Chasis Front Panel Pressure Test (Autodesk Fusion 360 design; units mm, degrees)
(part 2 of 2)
sketch "Sketch8" plane through (0, 0, 0) normal (-1, 0, 0) x axis (0, -1, 0)
  line L1 (-12.8306, 47.5808) -> (-6.8306, 47.5808)
  line L2 (-12.8306, 77.5808) -> (-12.8306, 47.5808)
  line L3 (-6.8306, 77.5808) -> (-12.8306, 77.5808)
  line L4 (-6.8306, 97.5808) -> (-6.8306, 77.5808)
  line L5 (-12.8306, 97.5808) -> (-6.8306, 97.5808)
  line L6 (-12.8306, 112.5808) -> (-12.8306, 97.5808)
  line L7 (-60.8306, 112.5808) -> (-12.8306, 112.5808)
  line L8 (-60.8306, 118.5808) -> (-60.8306, 112.5808)
  line L9 (-140.8306, 118.5808) -> (-60.8306, 118.5808)
  line L10 (-140.8306, 112.5808) -> (-140.8306, 118.5808)
  line L11 (-194.8306, 112.5808) -> (-140.8306, 112.5808)
  line L12 (-194.8306, 118.5808) -> (-194.8306, 112.5808)
  line L13 (-274.8306, 118.5808) -> (-194.8306, 118.5808)
  line L14 (-274.8306, 112.5808) -> (-274.8306, 118.5808)
  line L15 (-322.8306, 112.5808) -> (-274.8306, 112.5808)
  line L16 (-322.8306, 97.5808) -> (-322.8306, 112.5808)
  line L17 (-328.8306, 97.5808) -> (-322.8306, 97.5808)
  line L18 (-328.8306, 77.5808) -> (-328.8306, 97.5808)
  line L19 (-322.8306, 77.5808) -> (-328.8306, 77.5808)
  line L20 (-322.8306, 47.5808) -> (-322.8306, 77.5808)
  line L21 (-328.8306, 47.5808) -> (-322.8306, 47.5808)
  line L22 (-328.8306, 27.5808) -> (-328.8306, 47.5808)
  line L23 (-322.8306, 27.5808) -> (-328.8306, 27.5808)
  line L24 (-322.8306, 12.5808) -> (-322.8306, 27.5808)
  line L25 (-274.8306, 12.5808) -> (-322.8306, 12.5808)
  line L26 (-274.8306, 6.5808) -> (-274.8306, 12.5808)
  line L27 (-194.8306, 6.5808) -> (-274.8306, 6.5808)
  line L28 (-194.8306, 12.5808) -> (-194.8306, 6.5808)
  line L29 (-140.8306, 12.5808) -> (-194.8306, 12.5808)
  line L30 (-140.8306, 6.5808) -> (-140.8306, 12.5808)
  line L31 (-60.8306, 6.5808) -> (-140.8306, 6.5808)
  line L32 (-60.8306, 12.5808) -> (-60.8306, 6.5808)
  line L33 (-12.8306, 12.5808) -> (-60.8306, 12.5808)
  line L34 (-12.8306, 27.5808) -> (-12.8306, 12.5808)
  line L35 (-6.8306, 27.5808) -> (-12.8306, 27.5808)
  line L36 (-6.8306, 47.5808) -> (-6.8306, 27.5808)
  line L37 (-295.8805, 70.6308) -> (-295.8805, 54.5308)
  line L38 (-293.4805, 70.6308) -> (-295.8805, 70.6308)
  line L39 (-293.4805, 54.5308) -> (-293.4805, 70.6308)
  line L40 (-295.8805, 54.5308) -> (-293.4805, 54.5308)
  line L41 (-48.6306, 76.0808) -> (-48.6306, 49.0808)
  line L42 (-35.6306, 76.0808) -> (-48.6306, 76.0808)
  line L43 (-35.6306, 49.0808) -> (-35.6306, 76.0808)
  line L44 (-48.6306, 49.0808) -> (-35.6306, 49.0808)
  line L45 (-272.9555, 53.2308) -> (-270.6055, 53.2308)
  line L46 (-274.0555, 70.8308) -> (-274.0555, 54.3308)
  line L47 (-270.6055, 71.9308) -> (-272.9555, 71.9308)
  line L48 (-270.6055, 73.5808) -> (-270.6055, 71.9308)
  line L49 (-267.6055, 71.9308) -> (-267.6055, 73.5808)
  line L50 (-265.2555, 71.9308) -> (-267.6055, 71.9308)
  line L51 (-264.1555, 54.3308) -> (-264.1555, 70.8308)
  line L52 (-267.6055, 53.2308) -> (-265.2555, 53.2308)
  line L53 (-267.6055, 51.5808) -> (-267.6055, 53.2308)
  line L54 (-270.6055, 53.2308) -> (-270.6055, 51.5808)
  line L55 (-204.3306, 80.0808) -> (-204.3306, 55.0808)
  line L56 (-131.3306, 80.0808) -> (-204.3306, 80.0808)
  line L57 (-131.3306, 55.0808) -> (-131.3306, 80.0808)
  line L58 (-204.3306, 55.0808) -> (-131.3306, 55.0808)
  line L59 (-235.1305, 53.2308) -> (-235.1305, 51.5808)
  line L60 (-237.4805, 53.2308) -> (-235.1305, 53.2308)
  line L61 (-238.5805, 70.8308) -> (-238.5805, 54.3308)
  line L62 (-235.1305, 71.9308) -> (-237.4805, 71.9308)
  line L63 (-235.1305, 73.5808) -> (-235.1305, 71.9308)
  line L64 (-232.1305, 71.9308) -> (-232.1305, 73.5808)
  line L65 (-229.7805, 71.9308) -> (-232.1305, 71.9308)
  line L66 (-228.6805, 54.3308) -> (-228.6805, 70.8308)
  line L67 (-232.1305, 53.2308) -> (-229.7805, 53.2308)
  line L68 (-232.1305, 51.5808) -> (-232.1305, 53.2308)
  line L69 (-14.8306, 112.5808) -> (-30.8306, 112.5808)
  line L70 (-25.5806, 91.5808) -> (-25.5806, 107.0808)
  line L71 (-20.0806, 107.0808) -> (-20.0806, 91.5808)
  line L72 (-14.8306, 107.0808) -> (-14.8306, 112.5808)
  line L73 (-30.8306, 107.0808) -> (-14.8306, 107.0808)
  line L74 (-20.0806, 91.5808) -> (-25.5806, 91.5808)
  line L75 (-30.8306, 112.5808) -> (-30.8306, 107.0808)
  circle C1 centre (-22.8306, 27.5808) radius 2.05
  circle C2 centre (-312.8306, 27.5808) radius 2.05
  circle C3 centre (-22.8306, 97.5808) radius 2.05
  circle C4 centre (-312.8306, 97.5808) radius 2.05
  circle C5 centre (-205.3306, 52.0808) radius 1.5
  circle C6 centre (-185.3306, 33.8308) radius 3
  circle C7 centre (-88.4306, 62.5808) radius 11
  circle C8 centre (-200.3306, 33.8308) radius 3
  circle C9 centre (-205.3306, 83.0808) radius 1.5
  arc A1 centre (-272.9555, 54.3308) radius 1.1 clockwise from (-272.9555, 53.2308) to (-274.0555, 54.3308)
  arc A2 centre (-272.9555, 70.8308) radius 1.1 clockwise from (-274.0555, 70.8308) to (-272.9555, 71.9308)
  arc A3 centre (-269.1055, 73.5808) radius 1.5 clockwise from (-270.6055, 73.5808) to (-267.6055, 73.5808)
  arc A4 centre (-265.2555, 70.8308) radius 1.1 clockwise from (-265.2555, 71.9308) to (-264.1555, 70.8308)
  arc A5 centre (-265.2555, 54.3308) radius 1.1 clockwise from (-264.1555, 54.3308) to (-265.2555, 53.2308)
  arc A6 centre (-269.1055, 51.5808) radius 1.5 clockwise from (-267.6055, 51.5808) to (-270.6055, 51.5808)
  circle C10 centre (-130.3306, 83.0808) radius 1.5
  circle C11 centre (-150.3306, 33.8308) radius 3
  circle C12 centre (-135.3306, 33.8308) radius 3
  circle C13 centre (-130.3306, 52.0808) radius 1.5
  arc A7 centre (-237.4805, 54.3308) radius 1.1 clockwise from (-237.4805, 53.2308) to (-238.5805, 54.3308)
  arc A8 centre (-237.4805, 70.8308) radius 1.1 clockwise from (-238.5805, 70.8308) to (-237.4805, 71.9308)
  arc A9 centre (-233.6305, 73.5808) radius 1.5 clockwise from (-235.1305, 73.5808) to (-232.1305, 73.5808)
  arc A10 centre (-229.7805, 70.8308) radius 1.1 clockwise from (-229.7805, 71.9308) to (-228.6805, 70.8308)
  arc A11 centre (-229.7805, 54.3308) radius 1.1 clockwise from (-228.6805, 54.3308) to (-229.7805, 53.2308)
  arc A12 centre (-233.6305, 51.5808) radius 1.5 clockwise from (-232.1305, 51.5808) to (-235.1305, 51.5808)
  circle C14 centre (-22.8306, 97.5808) radius 2.5
extrude "Extrude10" add sketch "Sketch8" profile of L7 L69 L70 L71 L72 L73 L74 L75 C14 along normal blind 0.01
sketch "Sketch9" plane through (0, 0, 0) normal (-1, 0, 0) x axis (0, -1, 0)
  line L1 (-235.1305, 53.2308) -> (-235.1305, 51.5808)
  line L2 (-237.4805, 53.2308) -> (-235.1305, 53.2308)
  line L3 (-238.5805, 70.8308) -> (-238.5805, 54.3308)
  line L4 (-235.1305, 71.9308) -> (-237.4805, 71.9308)
  line L5 (-235.1305, 73.5808) -> (-235.1305, 71.9308)
  line L6 (-232.1305, 71.9308) -> (-232.1305, 73.5808)
  line L7 (-229.7805, 71.9308) -> (-232.1305, 71.9308)
  line L8 (-228.6805, 54.3308) -> (-228.6805, 70.8308)
  line L9 (-232.1305, 53.2308) -> (-229.7805, 53.2308)
  line L10 (-232.1305, 51.5808) -> (-232.1305, 53.2308)
  line L11 (-204.3306, 80.0808) -> (-204.3306, 55.0808)
  line L12 (-131.3306, 80.0808) -> (-204.3306, 80.0808)
  line L13 (-131.3306, 55.0808) -> (-131.3306, 80.0808)
  line L14 (-204.3306, 55.0808) -> (-131.3306, 55.0808)
  line L15 (-272.9555, 53.2308) -> (-270.6055, 53.2308)
  line L16 (-274.0555, 70.8308) -> (-274.0555, 54.3308)
  line L17 (-270.6055, 71.9308) -> (-272.9555, 71.9308)
  line L18 (-270.6055, 73.5808) -> (-270.6055, 71.9308)
  line L19 (-267.6055, 71.9308) -> (-267.6055, 73.5808)
  line L20 (-265.2555, 71.9308) -> (-267.6055, 71.9308)
  line L21 (-264.1555, 54.3308) -> (-264.1555, 70.8308)
  line L22 (-267.6055, 53.2308) -> (-265.2555, 53.2308)
  line L23 (-267.6055, 51.5808) -> (-267.6055, 53.2308)
  line L24 (-270.6055, 53.2308) -> (-270.6055, 51.5808)
  line L25 (-48.6306, 76.0808) -> (-48.6306, 49.0808)
  line L26 (-35.6306, 76.0808) -> (-48.6306, 76.0808)
  line L27 (-35.6306, 49.0808) -> (-35.6306, 76.0808)
  line L28 (-48.6306, 49.0808) -> (-35.6306, 49.0808)
  line L29 (-295.8805, 70.6308) -> (-295.8805, 54.5308)
  line L30 (-293.4805, 70.6308) -> (-295.8805, 70.6308)
  line L31 (-293.4805, 54.5308) -> (-293.4805, 70.6308)
  line L32 (-295.8805, 54.5308) -> (-293.4805, 54.5308)
  line L33 (-14.8306, 107.0808) -> (-14.8306, 112.5808)
  line L34 (-20.0806, 107.0808) -> (-14.8306, 107.0808)
  line L35 (-20.0806, 91.5808) -> (-20.0806, 107.0808)
  line L36 (-25.5806, 91.5808) -> (-20.0806, 91.5808)
  line L37 (-25.5806, 107.0808) -> (-25.5806, 91.5808)
  line L38 (-30.8306, 107.0808) -> (-25.5806, 107.0808)
  line L39 (-30.8306, 112.5808) -> (-30.8306, 107.0808)
  line L40 (-60.8306, 112.5808) -> (-30.8306, 112.5808)
  line L41 (-60.8306, 118.5808) -> (-60.8306, 112.5808)
  line L42 (-140.8306, 118.5808) -> (-60.8306, 118.5808)
  line L43 (-140.8306, 112.5808) -> (-140.8306, 118.5808)
  line L44 (-194.8306, 112.5808) -> (-140.8306, 112.5808)
  line L45 (-194.8306, 118.5808) -> (-194.8306, 112.5808)
  line L46 (-274.8306, 118.5808) -> (-194.8306, 118.5808)
  line L47 (-274.8306, 112.5808) -> (-274.8306, 118.5808)
  line L48 (-322.8306, 112.5808) -> (-274.8306, 112.5808)
  line L49 (-322.8306, 97.5808) -> (-322.8306, 112.5808)
  line L50 (-328.8306, 97.5808) -> (-322.8306, 97.5808)
  line L51 (-328.8306, 77.5808) -> (-328.8306, 97.5808)
  line L52 (-322.8306, 77.5808) -> (-328.8306, 77.5808)
  line L53 (-322.8306, 47.5808) -> (-322.8306, 77.5808)
  line L54 (-328.8306, 47.5808) -> (-322.8306, 47.5808)
  line L55 (-328.8306, 27.5808) -> (-328.8306, 47.5808)
  line L56 (-322.8306, 27.5808) -> (-328.8306, 27.5808)
  line L57 (-322.8306, 12.5808) -> (-322.8306, 27.5808)
  line L58 (-274.8306, 12.5808) -> (-322.8306, 12.5808)
  line L59 (-274.8306, 6.5808) -> (-274.8306, 12.5808)
  line L60 (-194.8306, 6.5808) -> (-274.8306, 6.5808)
  line L61 (-194.8306, 12.5808) -> (-194.8306, 6.5808)
  line L62 (-140.8306, 12.5808) -> (-194.8306, 12.5808)
  line L63 (-140.8306, 6.5808) -> (-140.8306, 12.5808)
  line L64 (-60.8306, 6.5808) -> (-140.8306, 6.5808)
  line L65 (-60.8306, 12.5808) -> (-60.8306, 6.5808)
  line L66 (-12.8306, 12.5808) -> (-60.8306, 12.5808)
  line L67 (-12.8306, 27.5808) -> (-12.8306, 12.5808)
  line L68 (-6.8306, 27.5808) -> (-12.8306, 27.5808)
  line L69 (-6.8306, 47.5808) -> (-6.8306, 27.5808)
  line L70 (-12.8306, 47.5808) -> (-6.8306, 47.5808)
  line L71 (-12.8306, 77.5808) -> (-12.8306, 47.5808)
  line L72 (-6.8306, 77.5808) -> (-12.8306, 77.5808)
  line L73 (-6.8306, 97.5808) -> (-6.8306, 77.5808)
  line L74 (-12.8306, 97.5808) -> (-6.8306, 97.5808)
  line L75 (-12.8306, 112.5808) -> (-12.8306, 97.5808)
  line L76 (-14.8306, 112.5808) -> (-12.8306, 112.5808)
  line L77 (-194.8306, 12.5808) -> (-274.8306, 12.5808)
  line L78 (-194.8306, 6.5808) -> (-194.8306, 12.5808)
  line L79 (-274.8306, 6.5808) -> (-194.8306, 6.5808)
  line L80 (-274.8306, 12.5808) -> (-274.8306, 6.5808)
  line L81 (-60.8306, 12.5808) -> (-140.8306, 12.5808)
  line L82 (-60.8306, 6.5808) -> (-60.8306, 12.5808)
  line L83 (-140.8306, 6.5808) -> (-60.8306, 6.5808)
  line L84 (-140.8306, 12.5808) -> (-140.8306, 6.5808)
  line L85 (-328.8306, 27.5808) -> (-322.8306, 27.5808)
  line L86 (-328.8306, 47.5808) -> (-328.8306, 27.5808)
  line L87 (-322.8306, 47.5808) -> (-328.8306, 47.5808)
  line L88 (-322.8306, 27.5808) -> (-322.8306, 47.5808)
  line L89 (-328.8306, 77.5808) -> (-322.8306, 77.5808)
  line L90 (-328.8306, 97.5808) -> (-328.8306, 77.5808)
  line L91 (-322.8306, 97.5808) -> (-328.8306, 97.5808)
  line L92 (-322.8306, 77.5808) -> (-322.8306, 97.5808)
  line L93 (-194.8306, 118.5808) -> (-274.8306, 118.5808)
  line L94 (-194.8306, 112.5808) -> (-194.8306, 118.5808)
  line L95 (-274.8306, 112.5808) -> (-194.8306, 112.5808)
  line L96 (-274.8306, 118.5808) -> (-274.8306, 112.5808)
  line L97 (-60.8306, 118.5808) -> (-140.8306, 118.5808)
  line L98 (-60.8306, 112.5808) -> (-60.8306, 118.5808)
  line L99 (-140.8306, 112.5808) -> (-60.8306, 112.5808)
  line L100 (-140.8306, 118.5808) -> (-140.8306, 112.5808)
  line L101 (-6.8306, 97.5808) -> (-12.8306, 97.5808)
  line L102 (-6.8306, 77.5808) -> (-6.8306, 97.5808)
  line L103 (-12.8306, 77.5808) -> (-6.8306, 77.5808)
  line L104 (-12.8306, 97.5808) -> (-12.8306, 77.5808)
  line L105 (-6.8306, 47.5808) -> (-12.8306, 47.5808)
  line L106 (-6.8306, 27.5808) -> (-6.8306, 47.5808)
  line L107 (-12.8306, 27.5808) -> (-6.8306, 27.5808)
  line L108 (-12.8306, 47.5808) -> (-12.8306, 27.5808)
  arc A1 centre (-237.4805, 54.3308) radius 1.1 clockwise from (-237.4805, 53.2308) to (-238.5805, 54.3308)
  arc A2 centre (-237.4805, 70.8308) radius 1.1 clockwise from (-238.5805, 70.8308) to (-237.4805, 71.9308)
  arc A3 centre (-233.6305, 73.5808) radius 1.5 clockwise from (-235.1305, 73.5808) to (-232.1305, 73.5808)
  arc A4 centre (-229.7805, 70.8308) radius 1.1 clockwise from (-229.7805, 71.9308) to (-228.6805, 70.8308)
  arc A5 centre (-229.7805, 54.3308) radius 1.1 clockwise from (-228.6805, 54.3308) to (-229.7805, 53.2308)
  arc A6 centre (-233.6305, 51.5808) radius 1.5 clockwise from (-232.1305, 51.5808) to (-235.1305, 51.5808)
  circle C1 centre (-130.3306, 52.0808) radius 1.5
  circle C2 centre (-135.3306, 33.8308) radius 3
  circle C3 centre (-150.3306, 33.8308) radius 3
  circle C4 centre (-130.3306, 83.0808) radius 1.5
  arc A7 centre (-272.9555, 54.3308) radius 1.1 clockwise from (-272.9555, 53.2308) to (-274.0555, 54.3308)
  arc A8 centre (-272.9555, 70.8308) radius 1.1 clockwise from (-274.0555, 70.8308) to (-272.9555, 71.9308)
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  point P95 (-194.8306, 6.5808)
  point P116 (-194.8306, 6.5808)
  point P93 (-274.8306, 12.5808)
  point P114 (-274.8306, 12.5808)
  point P99 (-60.8306, 6.5808)
  point P120 (-60.8306, 6.5808)
  point P97 (-140.8306, 12.5808)
  point P118 (-140.8306, 12.5808)
  point P89 (-328.8306, 47.5808)
  point P124 (-328.8306, 47.5808)
  point P91 (-322.8306, 27.5808)
  point P122 (-322.8306, 27.5808)
  point P85 (-328.8306, 97.5808)
  point P128 (-328.8306, 97.5808)
  point P87 (-322.8306, 77.5808)
  point P126 (-322.8306, 77.5808)
  point P79 (-194.8306, 112.5808)
  point P132 (-194.8306, 112.5808)
  point P81 (-274.8306, 118.5808)
  point P130 (-274.8306, 118.5808)
  point P75 (-60.8306, 112.5808)
  point P136 (-60.8306, 112.5808)
  point P77 (-140.8306, 118.5808)
  point P134 (-140.8306, 118.5808)
  point P107 (-6.8306, 77.5808)
  point P140 (-6.8306, 77.5808)
  point P109 (-12.8306, 97.5808)
  point P138 (-12.8306, 97.5808)
  point P103 (-6.8306, 27.5808)
  point P144 (-6.8306, 27.5808)
  point P105 (-12.8306, 47.5808)
  point P142 (-12.8306, 47.5808)
  horizontal L77
  vertical L78
  horizontal L79
  vertical L80
  coincident P95 P116
  coincident P93 P114
  horizontal L81
  vertical L82
  horizontal L83
  vertical L84
  coincident P99 P120
  coincident P97 P118
  horizontal L85
  vertical L86
  horizontal L87
  vertical L88
  coincident P89 P124
  coincident P91 P122
  horizontal L89
  vertical L90
  horizontal L91
  vertical L92
  coincident P85 P128
  coincident P87 P126
  horizontal L93
  vertical L94
  horizontal L95
  vertical L96
  coincident P79 P132
  coincident P81 P130
  horizontal L97
  vertical L98
  horizontal L99
  vertical L100
  coincident P75 P136
  coincident P77 P134
  horizontal L101
  vertical L102
  horizontal L103
  vertical L104
  coincident P107 P140
  coincident P109 P138
  horizontal L105
  vertical L106
  horizontal L107
  vertical L108
  coincident P103 P144
  coincident P105 P142
extrude "Extrude11" add sketch "Sketch9" profile of L41 L42 L43 L45 L46 L47 L50 L51 L52 L54 L55 L56 L59 L60 L61 L63 L64 L65 L68 L69 L70 L72 L73 L74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 along normal blind 0.01 and against normal blind 6.01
